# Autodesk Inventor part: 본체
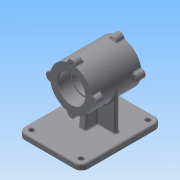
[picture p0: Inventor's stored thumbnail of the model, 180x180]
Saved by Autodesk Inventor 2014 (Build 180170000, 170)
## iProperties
Created: 2015-12
Part Number: 본체
Material: 일반
Document SubType Name: Modeling
Designer: Owner
Density: 1 g/cm^3
Appearance: 기본값
Author: Owner
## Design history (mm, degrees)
sketch "스케치1"
  geometry: L1 (-42.5, 0)-(42.5, 0); L2 (-42.5, 0)-(-42.5, 37); L3 (-42.5, 37)-(42.5, 37); L4 (42.5, 37)-(42.5, 0); L5 (-42.5, 23.5)-(-20.5, 23.5); L6 (-20.5, 23.5)-(-20.5, 21); L7 (-20.5, 21)-(20.5, 21); L8 (20.5, 21)-(20.5, 23.5); L9 (20.5, 23.5)-(42.5, 23.5); 2 further points
  constraints: 18 end point, 4 perpendicular, 2 horizontal, 2 point on line, 2 vertical, 1 coincident, 1 horizontal alignment, 1 midpoint, 1 parallel
  dimensions: "d0" = 74 diameter of L3 L1; "d1" = 85 distance of L2.end L3.end; "d2" = 47 diameter of L5 L1; "d3" = 42 diameter of L7 L1; "d4" = 47 diameter of L9 L1 (derived); "d5" = 22 distance of L5.start L5.end; "d6" = 41 distance of L6.end L7.end; "d7" = 22 distance of L8.end L9.end (derived)
revolve "회전1" sketch "스케치1" stored, may be unused: angle "d8" = 90 deg
sketch "스케치2"
  geometry: C1 r 23.5 at (0, 0) reference; C2 r 7 at (37, 0); 1 further point
  constraints: 2 horizontal alignment, 1 centre point, 1 other
  dimensions: "d9" = 14 diameter of C2
extrude "돌출1" join sketch "스케치2" distance "d10" = 15; taper "d11" = 0 deg
sketch "스케치3"
  geometry: L1 (27.5, 44)-(27.5, 36.338) reference; L2 (27.5, 37)-(-42.5, 37) reference; L3 (27.5, 37)-(30.048, 44); L4 (42.5, 44)-(27.5, 44) reference; L5 (42.5, 23.5)-(42.5, -23.5) reference; L6 (-42.5, 23.5)-(-42.5, -23.5) reference; L7 (42.5, 0)-(-42.5, 0); 1 further point
  constraints: 4 end point, 2 midpoint, 1 point on line
  dimensions: "d12" = 110 deg angle of L3 L2
revolve "회전2" sketch "스케치3" stored, may be unused: angle "d13" = 90 deg
sketch "스케치4"
  geometry: A1 r 7 centre (0, 0) between (-0.662, -6.969) and (-0.662, 6.969) reference
hole "구멍1" sketch "스케치4" at (0, 0) diameter "d14" = 3.242; stored, may be unused: countersink angle "d18" = 90 deg, drill point angle "d20" = 118 deg; dims "d15" = 9, "d16" = 4, "d17" = 2, "d19" = 11
node "작업 평면1"
sketch "스케치6"
  geometry: L1 (-80, 55)-(60, 55); L2 (60, 55)-(60, -55); L3 (60, -55)-(-80, -55); L4 (-80, -55)-(-80, 55); L5 (-42.5, -7)-(-42.5, 7) reference; L6 (-42.5, 6.969)-(-42.5, 36.338) reference; 4 further points
  constraints: 8 end point, 2 midpoint, 2 parallel, 1 horizontal, 1 horizontal alignment, 1 perpendicular
  dimensions: "d26" = 37.5 distance between parallel lines of L6 L4; "d27" = 140 distance of L1.start L1.end; "d28" = 110 distance of L1.end L2.end
extrude "돌출2" join sketch "스케치6" distance "d29" = 10; taper "d30" = 0 deg
sketch "스케치7"
  geometry: L1 (-80, 55)-(-80, -55) reference; L2 (-4, 37)-(4, 37); L3 (4, 37)-(4, -37); L4 (4, -37)-(-4, -37); L5 (-4, -37)-(-4, 37); L6 (-27.5, 37)-(27.5, 37) reference; L7 (-27.5, -37)-(27.5, -37) reference; 2 further points
  constraints: 8 end point, 2 horizontal alignment, 2 parallel, 1 horizontal, 1 midpoint, 1 perpendicular, 1 vertical alignment
  dimensions: "d31" = 80 distance from line of point (0, 37) L1 (derived); "d32" = 8 distance between parallel lines of L3 L5; "d33" = 76 distance between parallel lines of L5 L1 (derived)
extrude "돌출3" join sketch "스케치7" stored distance "d34" = 10; taper "d35" = 0 deg
sketch "스케치8"
  geometry: L1 (27.5, -37)-(-27.5, -37) reference; L2 (-60, -70)-(80, -70) reference; L3 (20.948, -37)-(25, -70); L4 (-20.948, -37)-(-25, -70); L5 (-4, -70)-(-4, 0) reference; L6 (4, 0)-(-4, 0) reference; L7 (-4, -70)-(-4, 0) reference; L8 (4, -70)-(-4, -70) reference; L9 (4, -70)-(4, 0) reference; 2 further points
  constraints: 4 end point, 4 point on line, 1 midpoint
  dimensions: "d36" = 97 deg angle of L2 L3; "d37" = 97 deg angle of L2 L4; "d38" = 25 distance of point (0, -70) L3.end; "d39" = 25 distance of L4.end point (0, -70); "d40" = 50 distance of L4.end L3.end (derived)
  node "투영된 루프1"
feature "리브1" dims "d41" = 1, "d42" = 12, "d43" = 0, "d44" = 0, "d45" = 1, "d46" = 1
feature "리브2" dims "d47" = 1, "d48" = 12, "d49" = 0, "d50" = 0, "d51" = 1, "d52" = 1
sketch "스케치10"
  geometry: L1 (60, -55)-(60, 55) reference; L2 (60, 55)-(-80, 55) reference; L3 (-80, 55)-(-80, -55) reference; L4 (-80, -55)-(60, -55) reference; 5 further points
  constraints: 2 horizontal alignment, 2 vertical alignment
  dimensions: "d53" = 12 distance from line of point (-68, 43) L3; "d54" = 12 distance from line of point (-68, 43) L2; "d55" = 12 distance from line of L2 point (48, 43) (derived); "d56" = 12 distance from line of point (48, 43) L1; "d57" = 12 distance from line of L4 point (48, -43)
hole "구멍2" sketch "스케치10" at (-68, 43), (48, 43), (48, -43), (-68, -43) diameter "d58" = 8; stored, may be unused: countersink angle "d62" = 90 deg, drill point angle "d64" = 118 deg; dims "d59" = 9, "d60" = 4, "d61" = 2, "d63" = 11
fillet "모깎기1" dims "d65" = 0.3
fillet "모깎기2" dims "d66" = 12, "d67" = 3
fillet "모깎기3" dims "d68" = 3
fillet "모깎기4" dims "d69" = 3
node "작업 평면3"
  node "작업 평면2"
sketch "스케치11"
  geometry: 2 further points
  constraints: 1 coincident, 1 other
feature "엠보싱1" sketch "스케치11" dims "d0" = 74, "d1" = 85, "d2" = 47, "d3" = 42, "d4" = 47 (derived), "d5" = 22, "d6" = 41, "d7" = 22 (derived), "d11" = 0, "d71" = 0.5, "d72" = 0
chamfer "모따기1" distance "d73" = 1; stored, may be unused: second distance "d74" = 2, angle "d75" = 45 deg
node "솔리드1"
pattern_circular "원형 패턴1" dims "d22" = 360 deg
mirror "대칭1"
other parameters: "d70" = 135 deg
